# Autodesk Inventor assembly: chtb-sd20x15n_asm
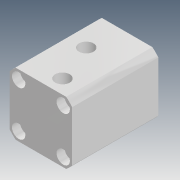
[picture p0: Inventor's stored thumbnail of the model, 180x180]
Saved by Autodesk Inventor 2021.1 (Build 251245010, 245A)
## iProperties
Company: Microsoft
Created: 2018-04
Part Number: chtb-sd20x15n_asm
Description: STEP AP214
Document SubType Name: Assembly
Designer: user
Title: chtb-sd20x15n_asm.STEP
Author: Windows
Revision Number: ÈÎºÎ
Sending System: SolidWorks 2015
Preprocessor: SwSTEP 2.0
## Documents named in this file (4)
- D:\Vault_2016\Projekty\Clamptek\Hydraulic\CHTB\CHTB-20\Inventor\CHTB-SD20x15N\chtb-sd20x15n_asm.iam
- D:\Vault_2016\Projekty\Clamptek\Hydraulic\CHTB\CHTB-20\Inventor\CHTB-SD20x15N\CHTB-SD20X15NBT.ipt
- D:\Vault_2016\Projekty\Clamptek\Hydraulic\CHTB\CHTB-20\Inventor\CHTB-SD20x15N\CHTB-SD20X15NHSG.ipt
- D:\Vault_2016\Projekty\Clamptek\Hydraulic\CHTB\CHTB-20\Inventor\CHTB-SD20x15N\QG.ipt
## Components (3 placed, 3 different names)
1. CHTB-SD20X15NBT_1
2. CHTB-SD20X15NHSG_2
3. QG_3
